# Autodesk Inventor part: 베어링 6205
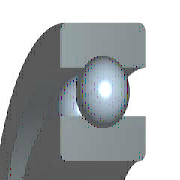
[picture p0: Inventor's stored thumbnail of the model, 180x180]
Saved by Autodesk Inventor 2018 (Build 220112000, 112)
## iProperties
Created: 2015-10
Part Number: 베어링 6205
Material: 강, 연강
Description: 깊은 그루브 볼 베어링
Document SubType Name: Modeling
Standard: KS B 2023
Designer: mdu
Standards Organization: KS
Language: ko-KR
Size Designation: 6205 - 25 x 52 x 15
Categories: <MemberInstance><Categories><Category DisplayName="샤프트 부품" InternalName="7f7aeb1f-a693-4053-b835-cee3144e0d98" Mnemonic="SHFT"><Category DisplayName="베어링" Inter
Density: 1 g/cm^3
Appearance: 노란색
IsCustomPart: 1
Author: mdu
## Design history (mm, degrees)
sketch "스케치" dims "d0" = 7.02 (= -0.26 x WD + 0.26 x BD)
  geometry: L1 (3.99, 19.25)-(11.01, 19.25); L2 (7.5, 19.25)-(7.5, 15.74); L3 (7.5, 19.25)-(7.5, 22.76); L4 (4.892, 16.901)-(0, 16.901); L5 (0, 12.5)-(15, 12.5); L6 (4.892, 21.599)-(0, 21.599); L7 (0, 26)-(15, 26); L8 (15, 12.5)-(15, 16.901); L9 (10.108, 16.901)-(15, 16.901); L10 (10.108, 21.599)-(15, 21.599); L11 (15, 26)-(15, 21.599); L12 (-1.4, 0)-(8.4, 0) reference; L13 (0, -0.3)-(0, 5.3) reference
  constraints: 22 end point, 4 point on line, 2 collinear, 2 perpendicular, 2 symmetric about line, 1 midpoint, 1 parallel, 14 other
  dimensions: "d9" = 25 diameter of L5 L12 (= WD); "d11" = 52 diameter of L7 L12 (= BD); "d12" = 15 distance between parallel lines of L8 L13 (= KB); "d13" = 33.802 diameter of L9 L12 (= 0.326 x BD + 0.674 x WD)
revolve "본체" stored, may be unused: angle "d6" = 90 deg
revolve "볼" stored, may be unused: angle "d7" = 90 deg
pattern_circular "IDS_ARRAYBALL[SIMPL:T]" dims angle "d3" = 360 deg
body "Solid1"
fillet "모깎기1" dims "d1" = 1 (= KRS)
other parameters: "WD" = 25 [user parameter; used in 5 equation terms], "BD" = 52 [user parameter; used in 5 equation terms], "KB" = 15 [user parameter; used in 1 equation term], "KRS" = 1 [user parameter; used in 1 equation term], "d4" = 0, "d5" = 0, "d8" = 0, "d14" = 0, "d15" = 0, "BBA" = 0 [user parameter], "BC0" = 7800000 [user parameter], "BC" = 1.4e+07 [user parameter], "BR" = 26 (= 0.5 x BD) [user parameter], "WR" = 12.5 (= 0.5 x WD) [user parameter]
